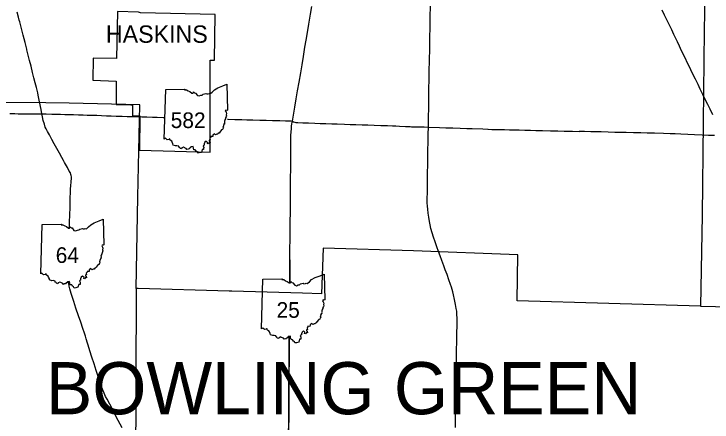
# Model space of a CAD drawing. Extents: x -232 to 448, y 619 to 1059.
# Drawn here: x 118.55 to 159.83, y 839.98 to 864.09 of the extents above; entities that cross this region are included whole.
import ezdxf

# ---------------------------------------------------------------- set-up
doc = ezdxf.new("R2010")
doc.units = 0
doc.layers.add('Default', color=7, linetype='Continuous')

msp = doc.modelspace()

# ---------------------------------------------------------------- linework, layer by layer
at = {"layer": 'Default'}
for p, q in [((127.439, 856.696), (127.521, 859.625)), ((127.439, 856.696), (127.521, 859.625)), ((120.134, 848.727), (120.216, 851.656)), ((120.134, 848.727), (120.216, 851.656)), ((133.192, 845.487), (133.274, 848.416)), ((133.192, 845.487), (133.274, 848.416))]:
    msp.add_line(p, q, dxfattribs=at)
for points in [[(159.393, 865.266), (159.369, 863.11), (159.296, 857.671), (159.237, 852.21), (159.147, 846.832)], [(135.015, 857.76), (135.07, 858.1), (135.159, 858.584), (135.243, 859.08), (135.325, 859.551), (135.412, 860.064), (135.508, 860.601), (135.584, 861.083), (135.666, 861.579), (135.759, 862.12), (135.826, 862.534), (135.906, 862.991), (135.988, 863.487), (136.084, 864.068), (136.166, 864.539)], [(143.011, 854.661), (143.012, 854.731), (143.019, 855.159), (143.029, 855.607), (143.03, 856.061), (143.04, 856.485), (143.051, 856.994), (143.056, 857.403), (143.064, 857.965), (143.072, 858.571), (143.084, 859.151), (143.091, 859.708), (143.099, 860.183), (143.108, 860.74), (143.118, 861.307), (143.132, 862.09), (143.143, 862.684), (143.152, 863.311), (143.162, 863.901), (143.176, 864.571)], [(118.865, 863.73), (118.824, 863.89), (118.747, 864.186)], [(130.451, 864.065), (126.027, 864.164), (125.908, 864.193), (124.664, 864.242), (124.619, 861.454), (123.239, 861.478)], [(125.997, 858.063), (125.964, 856.036), (130.147, 855.919), (130.153, 861.351), (130.418, 861.355), (130.451, 864.065)], [(159.875, 858.135), (159.712, 858.458), (159.573, 858.743), (159.428, 859.043), (159.289, 859.328), (159.131, 859.651), (159.002, 859.919), (158.843, 860.246), (158.661, 860.62), (158.487, 860.97), (158.383, 861.184), (158.231, 861.499), (158.029, 861.909), (157.894, 862.194), (157.777, 862.441), (157.681, 862.645), (157.578, 862.866), (157.447, 863.144), (157.304, 863.434), (157.169, 863.706), (157.018, 864.012), (156.869, 864.312)], [(119.318, 861.975), (119.307, 862.017), (119.207, 862.393), (119.091, 862.829), (118.972, 863.31), (118.893, 863.618), (118.865, 863.73)], [(119.954, 859.42), (119.934, 859.5), (119.875, 859.752), (119.81, 860.018), (119.731, 860.32), (119.656, 860.623), (119.562, 861.007), (119.476, 861.346), (119.397, 861.664), (119.318, 861.975)], [(123.239, 861.478), (123.219, 860.175), (124.601, 860.124), (124.593, 858.745), (124.744, 858.742), (125.115, 858.733), (125.457, 858.727), (125.565, 858.722), (125.561, 858.077), (125.997, 858.063)], [(125.768, 847.874), (125.87, 853.294), (125.994, 858.714), (121.819, 858.809), (120.432, 858.836), (117.754, 858.849), (115.033, 858.928), (115.073, 861.234)], [(127.521, 859.625), (128.657, 859.644), (128.64, 859.609), (128.747, 859.601), (128.861, 859.539), (128.957, 859.499), (129.075, 859.406), (129.145, 859.407), (129.175, 859.483), (129.229, 859.424), (129.293, 859.414), (129.404, 859.274), (129.496, 859.243), (129.605, 859.291), (129.687, 859.299), (129.747, 859.347), (129.903, 859.387), (129.946, 859.363), (130.029, 859.368), (130.07, 859.386), (130.142, 859.37), (130.269, 859.476), (130.4, 859.602), (130.6, 859.72), (130.9, 859.833), (131.137, 859.933), (131.171, 858.413)], [(127.521, 859.625), (128.657, 859.644), (128.64, 859.609), (128.747, 859.601), (128.861, 859.539), (128.957, 859.499), (129.075, 859.406), (129.145, 859.407), (129.175, 859.483), (129.229, 859.424), (129.293, 859.414), (129.404, 859.274), (129.496, 859.243), (129.605, 859.291), (129.687, 859.299), (129.747, 859.347), (129.903, 859.387), (129.946, 859.363), (130.029, 859.368), (130.07, 859.386), (130.142, 859.37), (130.269, 859.476), (130.4, 859.602), (130.6, 859.72), (130.9, 859.833), (131.137, 859.933), (131.171, 858.413)], [(120.205, 858.182), (120.156, 858.438), (120.063, 858.891), (119.986, 859.285), (119.954, 859.42)], [(118.303, 858.207), (118.599, 858.199), (118.793, 858.196)], [(118.793, 858.196), (118.82, 858.195), (119.271, 858.187), (119.69, 858.184), (120.016, 858.181), (120.205, 858.182)], [(121.473, 855.437), (121.381, 855.602), (121.234, 855.874), (121.083, 856.15), (120.931, 856.42), (120.792, 856.673), (120.647, 856.939), (120.531, 857.142), (120.446, 857.308), (120.403, 857.409), (120.348, 857.587), (120.284, 857.802), (120.237, 858.015), (120.205, 858.182)], [(120.205, 858.182), (120.461, 858.179), (120.789, 858.176), (121.099, 858.173), (121.304, 858.167), (121.564, 858.158), (121.806, 858.152), (122.071, 858.142), (122.36, 858.135), (122.643, 858.126), (122.88, 858.118)], [(131.171, 858.413), (131.136, 858.392), (131.082, 858.402), (131.045, 858.359), (131.091, 858.288), (131.112, 858.213), (131.093, 858.13), (131.112, 858.062), (131.099, 858.005), (131.065, 857.948), (131.053, 857.893), (131.024, 857.836), (131.026, 857.804), (130.999, 857.779), (131.004, 857.684), (130.99, 857.631), (130.994, 857.586), (130.949, 857.574), (130.96, 857.536), (130.931, 857.507), (130.937, 857.457), (130.905, 857.426), (130.936, 857.362), (130.911, 857.342), (130.89, 857.264), (130.832, 857.248), (130.717, 857.107), (130.676, 857.053), (130.63, 857.04), (130.605, 856.984), (130.548, 856.984), (130.463, 856.946), (130.408, 857.012), (130.311, 856.933), (130.3, 856.841), (130.178, 856.844), (130.183, 856.798), (130.155, 856.785), (130.13, 856.738), (130.145, 856.656), (130.088, 856.635), (130.095, 856.588), (130.131, 856.558), (130.148, 856.467), (130.087, 856.486), (130.037, 856.409), (129.986, 856.427), (130.002, 856.492), (129.916, 856.57), (129.834, 856.508), (129.791, 856.407), (129.791, 856.34), (129.73, 856.299), (129.769, 856.204), (129.762, 856.138), (129.763, 856.076), (129.687, 856.078), (129.64, 855.91)], [(131.171, 858.413), (131.136, 858.392), (131.082, 858.402), (131.045, 858.359), (131.091, 858.288), (131.112, 858.213), (131.093, 858.13), (131.112, 858.062), (131.099, 858.005), (131.065, 857.948), (131.053, 857.893), (131.024, 857.836), (131.026, 857.804), (130.999, 857.779), (131.004, 857.684), (130.99, 857.631), (130.994, 857.586), (130.949, 857.574), (130.96, 857.536), (130.931, 857.507), (130.937, 857.457), (130.905, 857.426), (130.936, 857.362), (130.911, 857.342), (130.89, 857.264), (130.832, 857.248), (130.717, 857.107), (130.676, 857.053), (130.63, 857.04), (130.605, 856.984), (130.548, 856.984), (130.463, 856.946), (130.408, 857.012), (130.311, 856.933), (130.3, 856.841), (130.178, 856.844), (130.183, 856.798), (130.155, 856.785), (130.13, 856.738), (130.145, 856.656), (130.088, 856.635), (130.095, 856.588), (130.131, 856.558), (130.148, 856.467), (130.087, 856.486), (130.037, 856.409), (129.986, 856.427), (130.002, 856.492), (129.916, 856.57), (129.834, 856.508), (129.791, 856.407), (129.791, 856.34), (129.73, 856.299), (129.769, 856.204), (129.762, 856.138), (129.763, 856.076), (129.687, 856.078), (129.64, 855.91)], [(122.88, 858.118), (122.907, 858.117), (123.188, 858.11), (123.441, 858.1), (123.726, 858.089), (124.019, 858.077), (124.304, 858.068), (124.601, 858.059), (124.943, 858.047), (125.249, 858.038), (125.522, 858.031), (125.78, 858.025), (126.102, 858.017), (126.41, 858.006), (126.734, 857.998), (127.021, 857.989), (127.373, 857.979), (127.476, 857.976)], [(131.184, 857.875), (131.222, 857.874), (131.614, 857.863), (132.032, 857.852), (132.311, 857.843), (132.684, 857.832), (133.088, 857.821), (133.463, 857.813), (133.839, 857.8), (134.269, 857.787), (134.614, 857.781), (134.934, 857.771), (135.015, 857.76)], [(134.856, 848.198), (134.856, 848.198), (134.856, 848.198), (134.858, 848.658), (134.862, 849.254), (134.865, 849.641), (134.872, 850.177), (134.877, 850.796), (134.879, 851.316), (134.889, 851.859), (134.895, 852.319), (134.893, 852.794), (134.9, 853.358), (134.909, 853.878), (134.91, 854.39), (134.915, 854.932), (134.918, 855.436), (134.92, 855.933), (134.925, 856.456), (134.926, 856.758), (134.929, 856.935), (134.939, 857.115), (134.954, 857.314), (134.969, 857.458), (134.986, 857.606), (135.015, 857.76)], [(135.015, 857.76), (135.084, 857.723), (135.16, 857.693), (135.219, 857.684), (135.328, 857.674), (135.629, 857.665), (135.974, 857.653), (136.339, 857.64), (136.658, 857.627), (136.995, 857.617), (137.341, 857.607), (137.667, 857.593), (138.092, 857.579), (138.434, 857.567), (138.76, 857.558), (139.133, 857.543), (139.482, 857.531), (139.853, 857.518), (140.25, 857.505), (140.634, 857.493), (140.929, 857.484), (141.136, 857.476), (141.341, 857.466), (141.706, 857.448), (141.981, 857.433)], [(141.981, 857.433), (142.048, 857.429), (142.288, 857.421), (142.796, 857.412), (143.056, 857.403), (143.703, 857.382), (144.08, 857.37), (144.383, 857.36)], [(144.383, 857.36), (144.505, 857.356), (144.928, 857.341), (145.322, 857.33), (145.638, 857.32), (146.278, 857.298), (146.563, 857.283), (146.594, 857.276), (146.811, 857.271), (146.833, 857.27)], [(146.833, 857.27), (147.076, 857.265), (147.3, 857.261), (147.546, 857.255), (147.852, 857.248), (148.104, 857.246), (148.42, 857.236), (148.763, 857.225), (149.1, 857.221), (149.406, 857.212), (149.812, 857.204), (150.276, 857.193), (150.709, 857.182), (151.074, 857.173), (151.569, 857.161), (151.961, 857.152), (151.998, 857.157), (152.045, 857.166), (152.283, 857.16), (152.657, 857.147), (152.965, 857.142), (153.277, 857.136), (153.681, 857.124), (154.075, 857.113), (154.438, 857.104), (154.752, 857.096), (155.192, 857.087), (155.608, 857.077), (155.998, 857.068), (156.423, 857.058), (156.948, 857.041), (157.357, 857.029), (157.642, 857.02), (157.991, 857.003), (158.387, 856.985), (158.787, 856.969), (159.234, 856.952), (159.614, 856.937), (159.971, 856.924)], [(129.64, 855.91), (129.508, 855.878), (129.416, 855.859), (129.383, 855.935), (129.317, 855.975), (129.275, 856.052), (129.18, 856.063), (129.158, 856.168), (129.147, 856.254), (129.018, 856.233), (128.982, 856.18), (128.937, 856.166), (128.91, 856.114), (128.847, 856.109), (128.78, 856.084), (128.736, 856.136), (128.627, 856.188), (128.577, 856.215), (128.474, 856.173), (128.452, 856.124), (128.37, 856.146), (128.35, 856.201), (128.301, 856.217), (128.29, 856.275), (128.183, 856.307), (128.102, 856.294), (127.959, 856.341), (127.95, 856.418), (127.901, 856.511), (127.876, 856.576), (127.785, 856.626), (127.766, 856.703), (127.737, 856.701), (127.711, 856.67), (127.61, 856.655), (127.57, 856.687), (127.514, 856.741), (127.439, 856.696)], [(129.64, 855.91), (129.508, 855.878), (129.416, 855.859), (129.383, 855.935), (129.317, 855.975), (129.275, 856.052), (129.18, 856.063), (129.158, 856.168), (129.147, 856.254), (129.018, 856.233), (128.982, 856.18), (128.937, 856.166), (128.91, 856.114), (128.847, 856.109), (128.78, 856.084), (128.736, 856.136), (128.627, 856.188), (128.577, 856.215), (128.474, 856.173), (128.452, 856.124), (128.37, 856.146), (128.35, 856.201), (128.301, 856.217), (128.29, 856.275), (128.183, 856.307), (128.102, 856.294), (127.959, 856.341), (127.95, 856.418), (127.901, 856.511), (127.876, 856.576), (127.785, 856.626), (127.766, 856.703), (127.737, 856.701), (127.711, 856.67), (127.61, 856.655), (127.57, 856.687), (127.514, 856.741), (127.439, 856.696)], [(121.836, 851.438), (121.844, 851.786), (121.856, 852.214), (121.867, 852.645), (121.883, 853.173), (121.898, 853.599), (121.901, 853.767), (121.916, 853.94), (121.937, 854.176), (121.955, 854.389), (121.956, 854.465), (121.943, 854.538), (121.922, 854.61), (121.89, 854.693), (121.821, 854.811), (121.709, 855.012), (121.546, 855.305), (121.473, 855.437)], [(144.649, 839.659), (144.655, 840.076), (144.667, 840.664), (144.674, 841.104), (144.679, 841.583), (144.687, 842.084), (144.697, 842.594), (144.707, 843.168), (144.715, 843.686), (144.724, 844.212), (144.731, 844.757), (144.745, 845.24), (144.757, 845.675), (144.758, 845.879), (144.754, 846.128), (144.744, 846.313), (144.735, 846.529), (144.703, 846.68), (144.656, 846.932), (144.6, 847.228), (144.546, 847.492), (144.505, 847.664), (144.468, 847.807), (144.42, 847.941), (144.366, 848.113), (144.266, 848.385), (144.156, 848.688), (144.054, 848.966), (143.966, 849.213), (143.85, 849.526), (143.746, 849.807), (143.659, 850.047), (143.557, 850.323), (143.447, 850.62), (143.353, 850.898), (143.281, 851.153), (143.205, 851.413), (143.153, 851.629), (143.117, 851.829), (143.078, 852.083), (143.045, 852.324), (143.013, 852.557), (142.999, 852.743), (142.992, 852.932), (142.989, 853.175), (142.994, 853.564), (142.997, 853.934), (143.008, 854.369), (143.011, 854.661)], [(120.216, 851.656), (121.352, 851.675), (121.334, 851.639), (121.441, 851.632), (121.555, 851.569), (121.652, 851.53), (121.77, 851.437), (121.84, 851.438), (121.87, 851.514), (121.924, 851.455), (121.988, 851.445), (122.099, 851.304), (122.19, 851.274), (122.3, 851.322), (122.382, 851.33), (122.441, 851.377), (122.597, 851.418), (122.641, 851.394), (122.723, 851.399), (122.765, 851.417), (122.837, 851.401), (122.964, 851.507), (123.094, 851.633), (123.295, 851.751), (123.595, 851.863), (123.832, 851.964), (123.866, 850.444)], [(120.216, 851.656), (121.352, 851.675), (121.334, 851.639), (121.441, 851.632), (121.555, 851.569), (121.652, 851.53), (121.77, 851.437), (121.84, 851.438), (121.87, 851.514), (121.924, 851.455), (121.988, 851.445), (122.099, 851.304), (122.19, 851.274), (122.3, 851.322), (122.382, 851.33), (122.441, 851.377), (122.597, 851.418), (122.641, 851.394), (122.723, 851.399), (122.765, 851.417), (122.837, 851.401), (122.964, 851.507), (123.094, 851.633), (123.295, 851.751), (123.595, 851.863), (123.832, 851.964), (123.866, 850.444)], [(123.866, 850.444), (123.831, 850.422), (123.776, 850.432), (123.74, 850.39), (123.785, 850.319), (123.807, 850.244), (123.788, 850.161), (123.806, 850.092), (123.794, 850.035), (123.759, 849.978), (123.748, 849.924), (123.718, 849.867), (123.721, 849.835), (123.693, 849.81), (123.698, 849.715), (123.684, 849.662), (123.689, 849.616), (123.644, 849.605), (123.654, 849.567), (123.626, 849.538), (123.632, 849.488), (123.599, 849.456), (123.631, 849.392), (123.606, 849.372), (123.585, 849.295), (123.527, 849.279), (123.411, 849.137), (123.37, 849.084), (123.325, 849.07), (123.299, 849.015), (123.243, 849.015), (123.158, 848.977), (123.102, 849.042), (123.006, 848.963), (122.995, 848.872), (122.872, 848.875), (122.877, 848.829), (122.85, 848.815), (122.825, 848.769), (122.839, 848.687), (122.782, 848.666), (122.789, 848.618), (122.826, 848.589), (122.842, 848.498), (122.781, 848.516), (122.731, 848.439), (122.68, 848.457), (122.697, 848.523), (122.61, 848.601), (122.528, 848.538), (122.486, 848.438), (122.485, 848.37), (122.424, 848.33), (122.463, 848.234), (122.456, 848.169), (122.457, 848.107), (122.381, 848.109), (122.335, 847.941)], [(123.866, 850.444), (123.831, 850.422), (123.776, 850.432), (123.74, 850.39), (123.785, 850.319), (123.807, 850.244), (123.788, 850.161), (123.806, 850.092), (123.794, 850.035), (123.759, 849.978), (123.748, 849.924), (123.718, 849.867), (123.721, 849.835), (123.693, 849.81), (123.698, 849.715), (123.684, 849.662), (123.689, 849.616), (123.644, 849.605), (123.654, 849.567), (123.626, 849.538), (123.632, 849.488), (123.599, 849.456), (123.631, 849.392), (123.606, 849.372), (123.585, 849.295), (123.527, 849.279), (123.411, 849.137), (123.37, 849.084), (123.325, 849.07), (123.299, 849.015), (123.243, 849.015), (123.158, 848.977), (123.102, 849.042), (123.006, 848.963), (122.995, 848.872), (122.872, 848.875), (122.877, 848.829), (122.85, 848.815), (122.825, 848.769), (122.839, 848.687), (122.782, 848.666), (122.789, 848.618), (122.826, 848.589), (122.842, 848.498), (122.781, 848.516), (122.731, 848.439), (122.68, 848.457), (122.697, 848.523), (122.61, 848.601), (122.528, 848.538), (122.486, 848.438), (122.485, 848.37), (122.424, 848.33), (122.463, 848.234), (122.456, 848.169), (122.457, 848.107), (122.381, 848.109), (122.335, 847.941)], [(142.168, 850.086), (136.837, 850.257), (136.74, 847.553), (135.614, 847.586), (131.439, 847.708), (131.277, 847.706), (125.899, 847.868), (125.768, 847.874)], [(159.147, 846.832), (148.295, 847.142), (148.353, 849.853), (142.168, 850.086)], [(134.866, 849.569), (134.856, 848.198)], [(122.335, 847.941), (122.202, 847.908), (122.11, 847.889), (122.078, 847.966), (122.012, 848.006), (121.969, 848.083), (121.875, 848.093), (121.852, 848.199), (121.842, 848.285), (121.712, 848.263), (121.677, 848.211), (121.631, 848.197), (121.604, 848.144), (121.542, 848.14), (121.475, 848.115), (121.431, 848.167), (121.321, 848.219), (121.272, 848.245), (121.168, 848.204), (121.146, 848.154), (121.064, 848.176), (121.045, 848.231), (120.995, 848.248), (120.984, 848.306), (120.878, 848.337), (120.797, 848.325), (120.653, 848.372), (120.644, 848.448), (120.596, 848.542), (120.57, 848.607), (120.479, 848.657), (120.461, 848.734), (120.432, 848.731), (120.405, 848.7), (120.305, 848.686), (120.264, 848.717), (120.208, 848.771), (120.134, 848.727)], [(122.335, 847.941), (122.202, 847.908), (122.11, 847.889), (122.078, 847.966), (122.012, 848.006), (121.969, 848.083), (121.875, 848.093), (121.852, 848.199), (121.842, 848.285), (121.712, 848.263), (121.677, 848.211), (121.631, 848.197), (121.604, 848.144), (121.542, 848.14), (121.475, 848.115), (121.431, 848.167), (121.321, 848.219), (121.272, 848.245), (121.168, 848.204), (121.146, 848.154), (121.064, 848.176), (121.045, 848.231), (120.995, 848.248), (120.984, 848.306), (120.878, 848.337), (120.797, 848.325), (120.653, 848.372), (120.644, 848.448), (120.596, 848.542), (120.57, 848.607), (120.479, 848.657), (120.461, 848.734), (120.432, 848.731), (120.405, 848.7), (120.305, 848.686), (120.264, 848.717), (120.208, 848.771), (120.134, 848.727)], [(133.274, 848.416), (134.41, 848.435), (134.392, 848.4), (134.5, 848.392), (134.614, 848.33), (134.71, 848.29), (134.828, 848.197), (134.898, 848.198), (134.928, 848.274), (134.982, 848.216), (135.046, 848.205), (135.157, 848.065), (135.248, 848.034), (135.358, 848.083), (135.44, 848.09), (135.5, 848.138), (135.656, 848.179), (135.699, 848.154), (135.782, 848.159), (135.823, 848.177), (135.895, 848.161), (136.022, 848.268), (136.152, 848.393), (136.353, 848.512), (136.653, 848.624), (136.89, 848.724), (136.924, 847.204)], [(133.274, 848.416), (134.41, 848.435), (134.392, 848.4), (134.5, 848.392), (134.614, 848.33), (134.71, 848.29), (134.828, 848.197), (134.898, 848.198), (134.928, 848.274), (134.982, 848.216), (135.046, 848.205), (135.157, 848.065), (135.248, 848.034), (135.358, 848.083), (135.44, 848.09), (135.5, 848.138), (135.656, 848.179), (135.699, 848.154), (135.782, 848.159), (135.823, 848.177), (135.895, 848.161), (136.022, 848.268), (136.152, 848.393), (136.353, 848.512), (136.653, 848.624), (136.89, 848.724), (136.924, 847.204)], [(124.95, 839.633), (124.717, 840.073), (124.503, 840.488), (124.328, 840.82), (124.211, 841.044), (124.06, 841.332), (123.972, 841.498), (123.883, 841.687), (123.816, 841.828), (123.737, 842.029), (123.648, 842.3), (123.546, 842.604), (123.408, 843.032), (123.284, 843.426), (123.161, 843.821), (123.042, 844.187), (122.943, 844.518), (122.883, 844.704), (122.836, 844.845), (122.823, 844.904), (122.81, 844.979), (122.787, 845.055), (122.724, 845.227), (122.626, 845.51), (122.501, 845.88), (122.368, 846.257), (122.216, 846.712), (122.089, 847.094), (121.994, 847.39), (121.936, 847.57), (121.885, 847.721), (121.848, 847.851), (121.818, 848.016), (121.794, 848.185), (121.782, 848.287)], [(125.768, 847.874), (125.733, 836.968), (109.325, 837.288), (109.26, 831.913)], [(136.924, 847.204), (136.889, 847.183), (136.835, 847.193), (136.798, 847.15), (136.843, 847.079), (136.865, 847.004), (136.846, 846.921), (136.865, 846.853), (136.852, 846.796), (136.818, 846.739), (136.806, 846.685), (136.777, 846.627), (136.779, 846.595), (136.751, 846.57), (136.756, 846.475), (136.742, 846.422), (136.747, 846.377), (136.702, 846.365), (136.712, 846.327), (136.684, 846.298), (136.69, 846.249), (136.658, 846.217), (136.689, 846.153), (136.664, 846.133), (136.643, 846.055), (136.585, 846.039), (136.469, 845.898), (136.429, 845.844), (136.383, 845.831), (136.358, 845.776), (136.301, 845.775), (136.216, 845.737), (136.161, 845.803), (136.064, 845.724), (136.053, 845.632), (135.931, 845.635), (135.935, 845.589), (135.908, 845.576), (135.883, 845.53), (135.898, 845.447), (135.84, 845.426), (135.847, 845.379), (135.884, 845.349), (135.9, 845.258), (135.839, 845.277), (135.79, 845.2), (135.738, 845.218), (135.755, 845.283), (135.669, 845.361), (135.587, 845.299), (135.544, 845.198), (135.543, 845.131), (135.482, 845.09), (135.522, 844.995), (135.514, 844.929), (135.516, 844.867), (135.439, 844.869), (135.393, 844.701)], [(136.924, 847.204), (136.889, 847.183), (136.835, 847.193), (136.798, 847.15), (136.843, 847.079), (136.865, 847.004), (136.846, 846.921), (136.865, 846.853), (136.852, 846.796), (136.818, 846.739), (136.806, 846.685), (136.777, 846.627), (136.779, 846.595), (136.751, 846.57), (136.756, 846.475), (136.742, 846.422), (136.747, 846.377), (136.702, 846.365), (136.712, 846.327), (136.684, 846.298), (136.69, 846.249), (136.658, 846.217), (136.689, 846.153), (136.664, 846.133), (136.643, 846.055), (136.585, 846.039), (136.469, 845.898), (136.429, 845.844), (136.383, 845.831), (136.358, 845.776), (136.301, 845.775), (136.216, 845.737), (136.161, 845.803), (136.064, 845.724), (136.053, 845.632), (135.931, 845.635), (135.935, 845.589), (135.908, 845.576), (135.883, 845.53), (135.898, 845.447), (135.84, 845.426), (135.847, 845.379), (135.884, 845.349), (135.9, 845.258), (135.839, 845.277), (135.79, 845.2), (135.738, 845.218), (135.755, 845.283), (135.669, 845.361), (135.587, 845.299), (135.544, 845.198), (135.543, 845.131), (135.482, 845.09), (135.522, 844.995), (135.514, 844.929), (135.516, 844.867), (135.439, 844.869), (135.393, 844.701)], [(159.147, 846.832), (164.497, 846.7), (164.496, 841.369), (164.482, 841.199), (164.467, 841.004), (164.46, 840.832), (164.455, 840.717), (164.444, 840.469), (164.435, 840.287), (164.417, 839.968), (164.329, 838.551), (164.33, 838.064), (164.336, 837.763), (164.341, 837.281), (164.344, 837.05), (164.348, 835.991), (164.349, 835.96), (164.279, 830.443), (169.711, 830.386), (175.075, 830.349), (175.068, 829.895)], [(135.393, 844.701), (135.261, 844.669), (135.168, 844.65), (135.136, 844.726), (135.07, 844.766), (135.027, 844.843), (134.933, 844.854), (134.91, 844.959), (134.9, 845.045), (134.771, 845.024), (134.735, 844.972), (134.689, 844.957), (134.663, 844.905), (134.6, 844.9), (134.533, 844.875), (134.489, 844.927), (134.379, 844.979), (134.33, 845.006), (134.227, 844.964), (134.205, 844.915), (134.122, 844.937), (134.103, 844.992), (134.053, 845.008), (134.042, 845.067), (133.936, 845.098), (133.855, 845.085), (133.711, 845.132), (133.703, 845.209), (133.654, 845.302), (133.628, 845.367), (133.538, 845.417), (133.519, 845.494), (133.49, 845.492), (133.464, 845.461), (133.363, 845.446), (133.323, 845.478), (133.266, 845.532), (133.192, 845.487)], [(135.393, 844.701), (135.261, 844.669), (135.168, 844.65), (135.136, 844.726), (135.07, 844.766), (135.027, 844.843), (134.933, 844.854), (134.91, 844.959), (134.9, 845.045), (134.771, 845.024), (134.735, 844.972), (134.689, 844.957), (134.663, 844.905), (134.6, 844.9), (134.533, 844.875), (134.489, 844.927), (134.379, 844.979), (134.33, 845.006), (134.227, 844.964), (134.205, 844.915), (134.122, 844.937), (134.103, 844.992), (134.053, 845.008), (134.042, 845.067), (133.936, 845.098), (133.855, 845.085), (133.711, 845.132), (133.703, 845.209), (133.654, 845.302), (133.628, 845.367), (133.538, 845.417), (133.519, 845.494), (133.49, 845.492), (133.464, 845.461), (133.363, 845.446), (133.323, 845.478), (133.266, 845.532), (133.192, 845.487)], [(134.831, 845.035), (134.8, 841.407), (134.812, 841.246), (134.758, 835.998), (134.767, 835.808), (134.719, 830.56), (134.724, 830.467), (134.602, 814.233)], [(134.786, 839.016), (134.792, 839.381), (134.794, 839.849), (134.796, 840.291), (134.799, 840.824), (134.804, 841.338), (134.808, 841.831), (134.812, 842.409), (134.816, 843.011), (134.814, 843.581), (134.818, 843.973), (134.819, 844.487), (134.824, 845.014), (134.824, 845.033)]]:
    msp.add_lwpolyline(points, dxfattribs=at)

# ---------------------------------------------------------------- texts
for s, height, p in [('HASKINS', 1.026, (123.988, 862.385)), ('582', 0.9234, (127.82, 857.349)), ('64', 0.9234, (121.02, 849.38)), ('25', 0.9234, (134.078, 846.14)), ('BOWLING GREEN', 3.07799, (120.435, 840.44))]:
    msp.add_text(s, height=height, dxfattribs=at).set_placement(p)

doc.saveas('drawing.dxf')
